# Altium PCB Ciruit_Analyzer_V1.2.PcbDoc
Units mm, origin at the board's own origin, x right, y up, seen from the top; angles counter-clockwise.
Board outline 62.74 x 37.85 mm, 2 copper layers (Top Layer, Bottom Layer); 14 components, 8 nets, 40 pads, 0 vias.
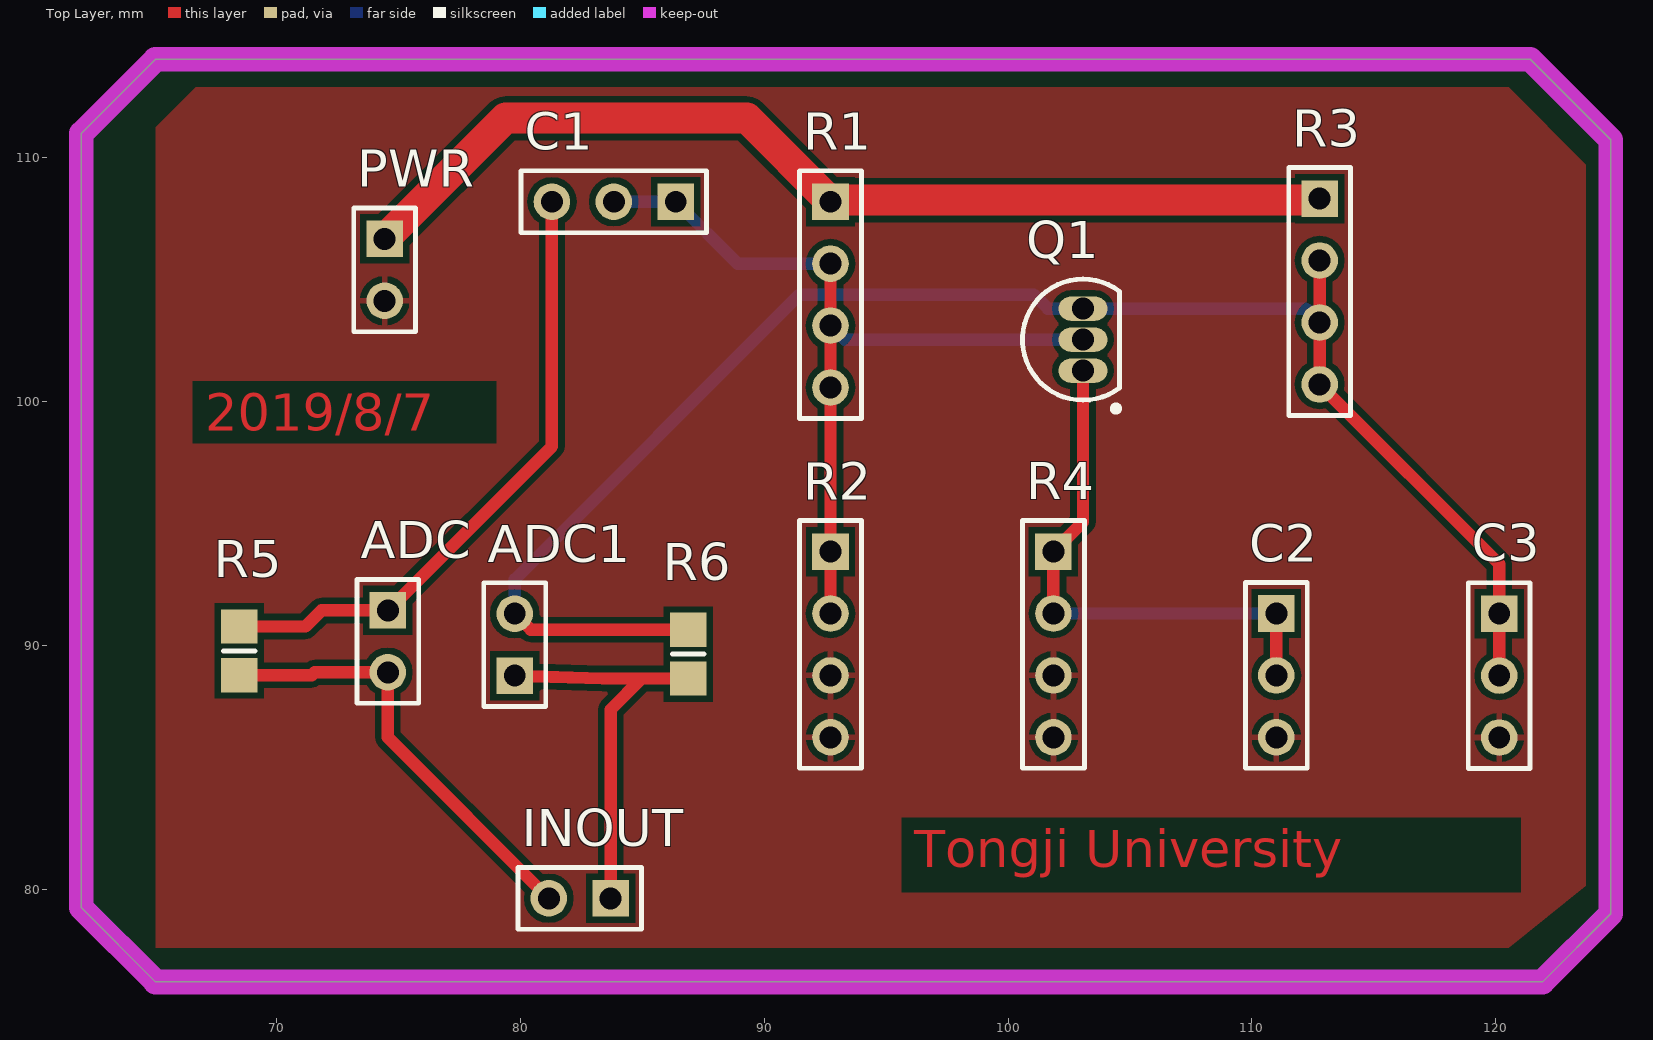
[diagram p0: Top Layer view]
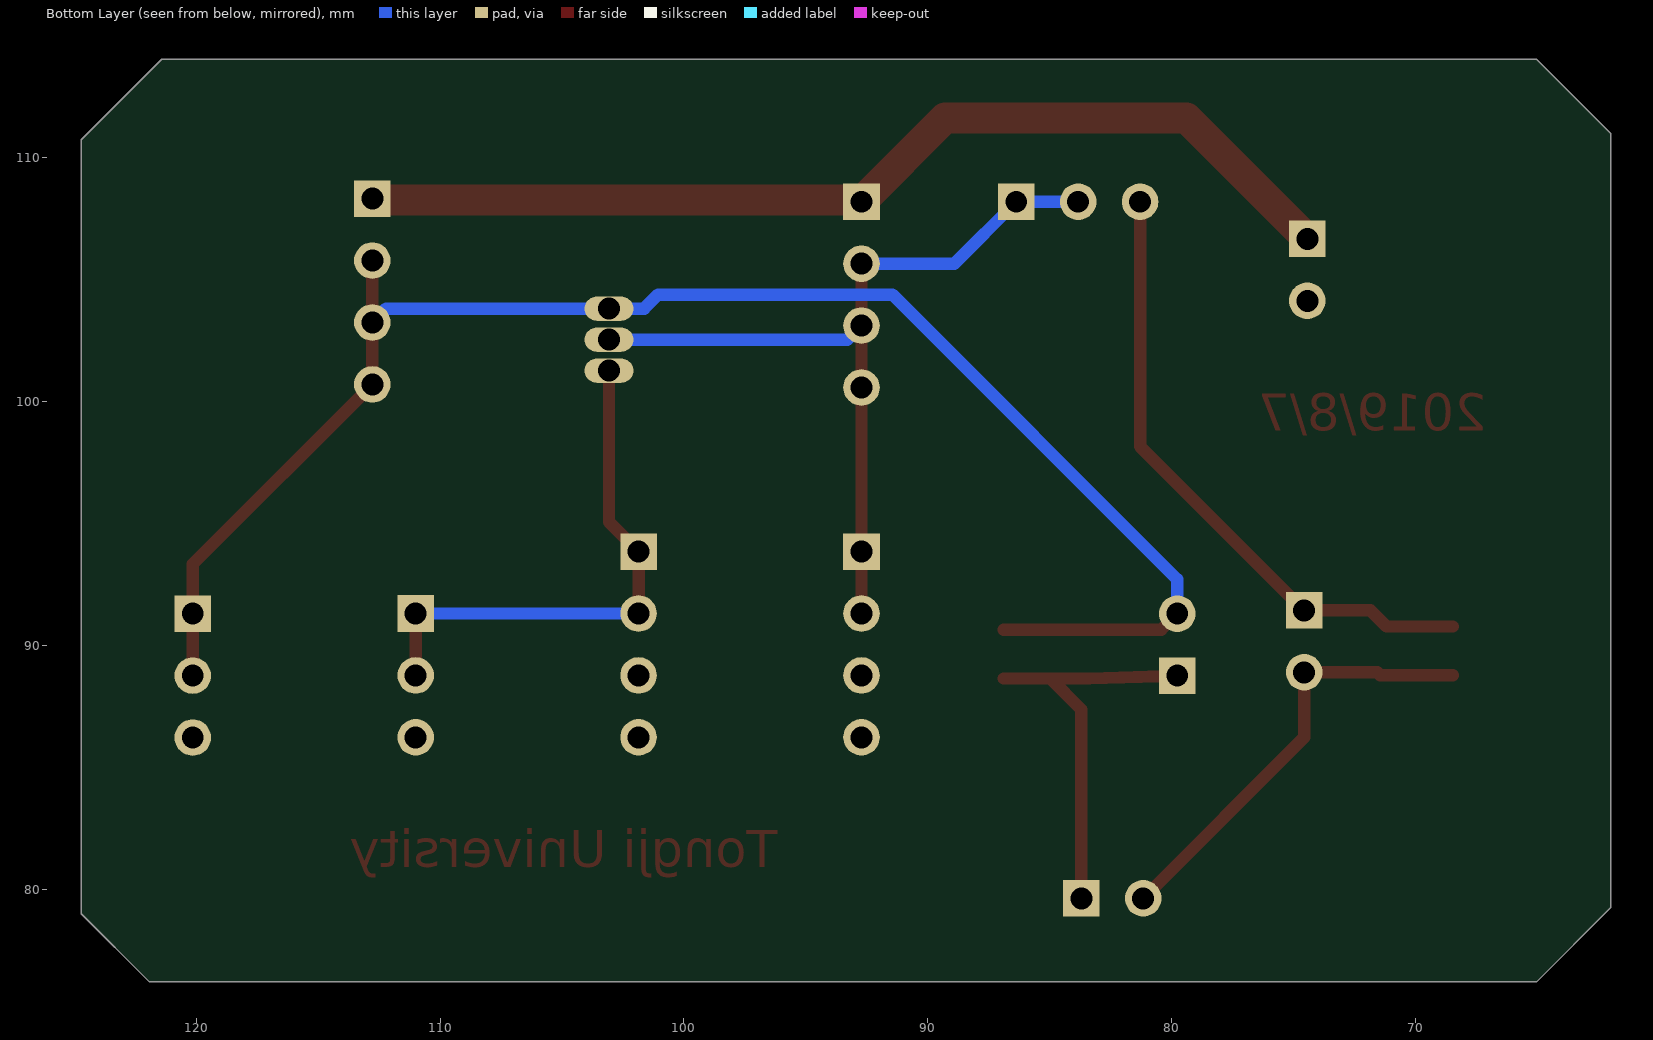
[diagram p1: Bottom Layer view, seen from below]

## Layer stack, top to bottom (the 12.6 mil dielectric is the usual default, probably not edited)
Top Solder: solder mask 0.0102, Solder Resist, Dk 3.5
Top Layer: signal copper 0.0356
Dielectric 1: dielectric 0.32, FR-4, Dk 4.8
Bottom Layer: signal copper 0.0356
Bottom Solder: solder mask 0.0102, Solder Resist, Dk 3.5

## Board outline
61.976,79.248 61.976,110.998 65.024,114.046 121.412,114.046 124.714,110.744 124.714,78.994 121.92,76.2 65.024,76.2

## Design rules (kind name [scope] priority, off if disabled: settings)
Clearance [All] p1: gap=0.254 ignorepadtopadclearanceinfootprint=FALSE except(0: Arc-Hole Track-Hole SMDPad-Hole THPad-Hole Via-Hole Fill-Hole Poly-Hole Region-Hole Text-Hole)
PolygonConnect [All] p1: connectstyle=Relief reliefconductorwidth=0.254 reliefentries=4 polygonreliefangle="90 Angle" airgapwidth=0.254
RoutingVias [All] p1: holewidth=0.711 width=1.27 viastyle="Through Hole" minholewidth=0.711 minwidth=1.27 maxholewidth=0.711 maxwidth=1.27
SolderMaskExpansion [All] p1: expansion=0.102
Width [All] p1: maxlimit=1.27 minlimit=0.254 preferedwidth=0.508 minimp=50.000000 maximp=50.000000 favimp=50.000000
30 further rules are at their usual default settings.

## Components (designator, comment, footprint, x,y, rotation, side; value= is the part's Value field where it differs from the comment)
ADC "" HDR1X2 74.549,91.44 r270 top
ADC1 "" HDR1X2 79.756,88.764 r90 top
C1 "10u" HDR1X3 86.36,108.204 r180 top
C2 "47uf" HDR1X3 110.998,91.313 r270 top
C3 "470pf" HDR1X3 120.142,91.304 r270 top
INOUT "" HDR1X2 83.693,79.629 r180 top
PWR "" HDR1X2 74.422,106.68 r270 top
Q1 "9013" TO-92A 103.068,102.548 r0 top
R1 "R1 43K" HDR1X4 92.71,108.204 r270 top
R2 "R2 15K" HDR1X4 92.71,93.853 r270 top
R3 "R3 2K" HDR1X4 112.776,108.331 r270 top
R4 "R4 1K" HDR1X4 101.854,93.853 r270 top
R5 "Res1" 6-0805_M 68.453,89.78 r90 top value=1K
R6 "Res1" 6-0805_M 86.868,89.644 r270 top value=1K

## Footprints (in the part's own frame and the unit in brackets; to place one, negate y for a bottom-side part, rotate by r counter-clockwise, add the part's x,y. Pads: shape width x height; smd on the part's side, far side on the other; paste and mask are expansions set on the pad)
6-0805_M [mm] "Chip Resistor, Body 2.0x1.2mm, IPC Low Density"
  rect 1.4x1.5 smd: 1(-1,0) 2(1,0)
  silkscreen extent 0,-0.65 0,0.65, body extent -1.07,-0.7 1.07,0.7, height 0.7
HDR1X2 [mm] "Connector; Header; 2 Position"
  rect 1.5x1.5 hole 0.9: 1(0,0)
  round 1.5 hole 0.9: 2(2.54,0)
  silkscreen extent -1.27,-1.27 3.81,1.27
HDR1X3 [mm] "Connector; Header; 3 Position"
  rect 1.5x1.5 hole 0.9: 1(0,0)
  round 1.5 hole 0.9: 2(2.54,0) 3(5.08,0)
  silkscreen extent -1.27,-1.27 6.35,1.27
HDR1X4 [mm] "Connector; Header; 4 Position"
  rect 1.5x1.5 hole 0.9: 1(0,0)
  round 1.5 hole 0.9: 2(2.54,0) 3(5.08,0) 4(7.62,0)
  silkscreen extent -1.27,-1.27 8.89,1.27
TO-92A [mm] "TO, Flat Index; 3 In-Line, Axial Leads; Body Dia. 4.5mm; Leads 0.51 x 0.48 mm (max)"
  oval 2x1 hole 0.9: 1(0,-1.27) 2(0,0) 3(0,1.27)
  silkscreen extent -2.48,-2.95 1.5,2.48, body extent -2.48,-2.5 1.5,2.5, height 6.86

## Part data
ADC ADC1 INOUT PWR: library part "Header 2", "Header, 2-Pin"
C1 C2 C3: library part "Header 3", "Header, 3-Pin"
Q1: library part 2N3904, "NPN General Purpose Amplifier"
R1 R2 R3 R4: library part "Header 4", "Header, 4-Pin"
R5 R6: "Resistor"

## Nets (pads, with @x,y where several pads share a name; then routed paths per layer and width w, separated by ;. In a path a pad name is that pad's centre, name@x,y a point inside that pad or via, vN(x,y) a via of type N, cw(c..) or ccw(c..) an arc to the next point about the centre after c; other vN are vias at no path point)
DC+12V: PWR.1 R1.1 R3.1 | length 41.9
  Top Layer w1.27: PWR.1 79.375,111.633 89.281,111.633 R1.1 92.773,108.267 112.712,108.267 R3.1
GND: C2.3 C3.3 PWR.2 R2.3 R2.4 R4.3 R4.4
NetC1_1: C1.1 C1.2 Q1.2 R1.2 R1.3 R1.4 R2.1 R2.2 | length 34.9
  Top Layer w0.508: R2.2 R2.1 R1.4 R1.3 R1.2
  Bottom Layer w0.508: C1.2 C1.1 88.9,105.664 R1.2 ; R1.3 93.286,102.548 Q1.2
NetC2_1: C2.1 C2.2 Q1.1 R4.1 R4.2 | length 22.2
  Top Layer w0.508: R4.2 R4.1 103.068,95.067 Q1.1 ; C2.2 C2.1
  Bottom Layer w0.508: R4.2 C2.1
Ui: ADC.1 C1.3 R5.2 | length 25.9
  Top Layer w0.508: R5.2 71.171,90.78 71.831,91.44 ADC.1 81.28,98.171 C1.3
UiRAW: ADC.2 INOUT.2 R5.1 | length 18.2
  Top Layer w0.508: R5.1 71.425,88.78 71.545,88.9 ADC.2 74.549,86.233 INOUT.2
Uo: ADC1.2 C3.1 C3.2 Q1.3 R3.2 R3.3 R3.4 R6.1 | length 67.2
  Top Layer w0.508: ADC1.2 80.416,90.644 R6.1 ; R3.2 R3.3 R3.4 120.142,93.345 C3.1 C3.2
  Bottom Layer w0.508: ADC1.2 79.756,92.71 91.44,104.394 101.049,104.394 101.625,103.818 Q1.3 112.209,103.818 R3.3
UoRAW: ADC1.1 INOUT.1 R6.2 | length 16.7
  Top Layer w0.508: ADC1.1 83.356,88.644 84.961,88.644 ; INOUT.1 83.693,87.376 84.961,88.644 ; R6.2 84.961,88.644

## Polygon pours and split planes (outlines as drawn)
GND on Top Layer "GND_L01_P000" (solid, remove dead copper, pour order 0): 65.024,111.252 66.675,112.903 120.523,112.903 123.698,109.728 123.698,80.137 120.523,77.597 65.024,77.597

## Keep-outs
Top Layer:
  lines w1.016: 61.976,79.248 61.976,107.823 61.976,110.998 65.024,114.046 121.412,114.046 124.714,110.744 124.714,78.994 121.92,76.2 65.024,76.2 61.976,79.248

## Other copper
Top Layer:
  text "2019/8/7" at 67.056,98.806 h1.52
  text "Tongji University" at 96.139,80.899 h1.52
